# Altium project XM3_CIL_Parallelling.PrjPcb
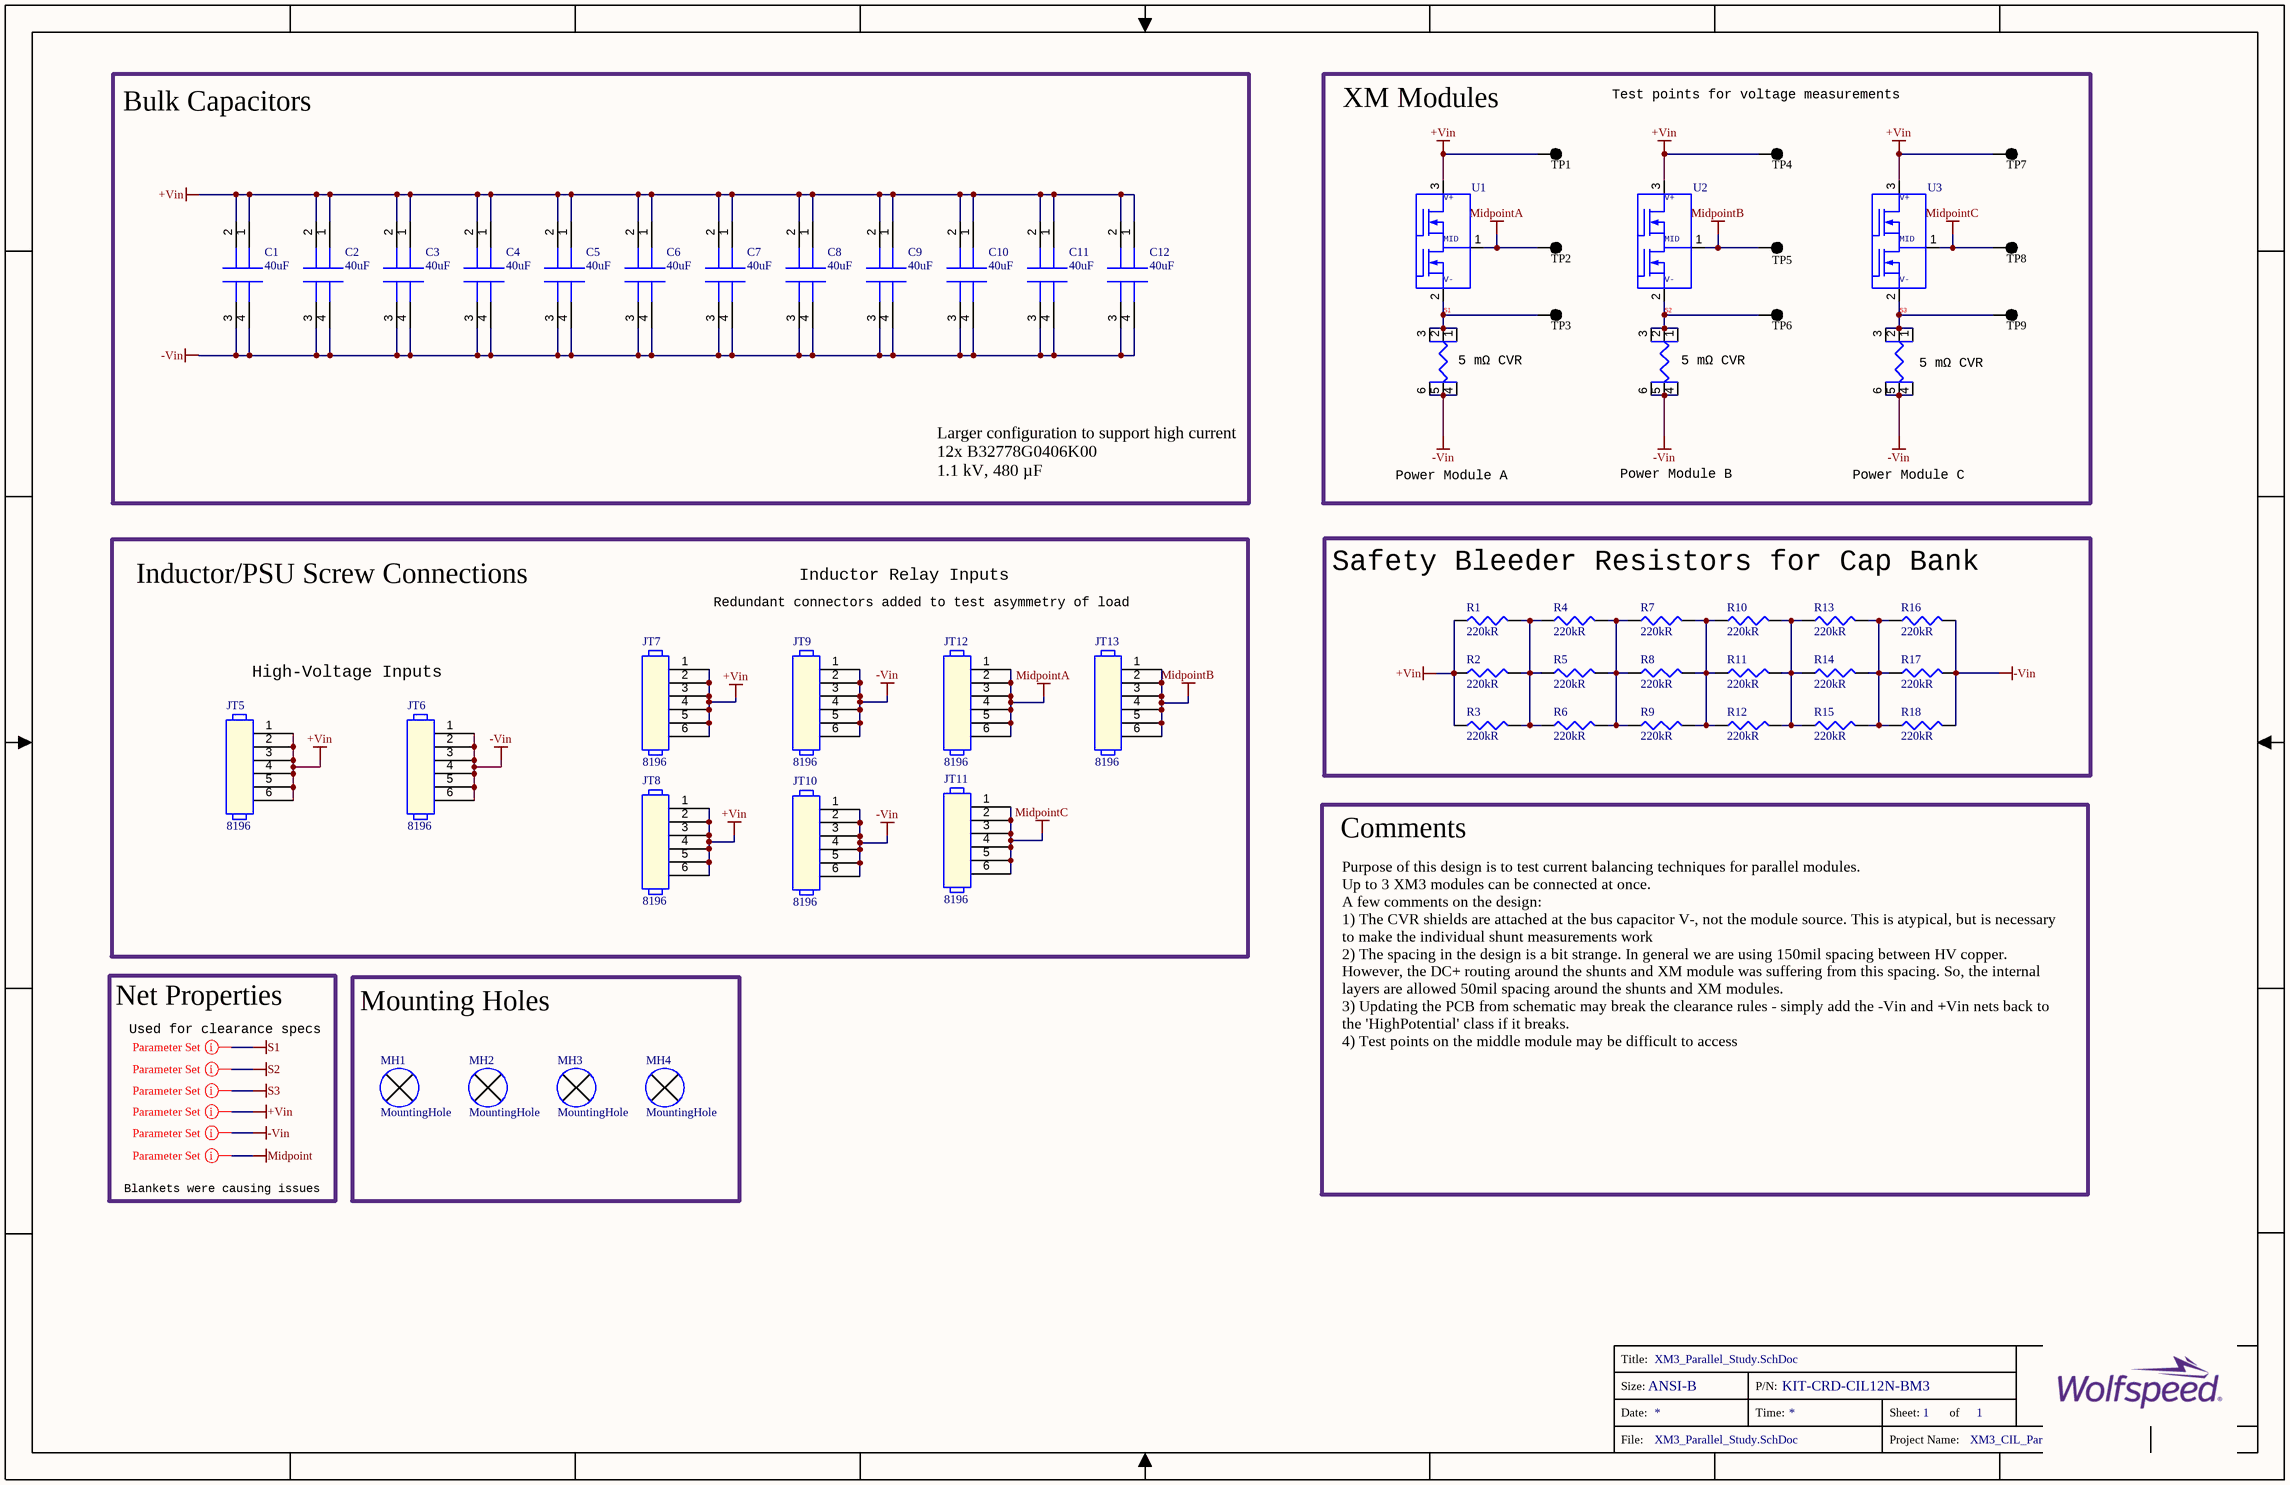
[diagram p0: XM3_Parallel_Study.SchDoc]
1 sheet, 58 parts. Net scope: global (net labels, ports and power ports of the same name join across sheets).
Board file: XM3_Parallel_Study.PcbDoc

## Sheet XM3_Parallel_Study.SchDoc
size 431 x 279 mm; DocumentNumber: KIT-CRD-CIL12N-BM3; Revision: 01; SheetNumber: 1; SheetTotal: 1

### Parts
C1  value 40uF  [C4AQSBW5220A3NJ]  (hidden comment: B32778G0406K000)
C2  value 40uF  [C4AQSBW5220A3NJ]  (hidden comment: B32778G0406K000)
C3  value 40uF  [C4AQSBW5220A3NJ]  (hidden comment: B32778G0406K000)
C4  value 40uF  [C4AQSBW5220A3NJ]  (hidden comment: B32778G0406K000)
C5  value 40uF  [C4AQSBW5220A3NJ]  (hidden comment: B32778G0406K000)
C6  value 40uF  [C4AQSBW5220A3NJ]  (hidden comment: B32778G0406K000)
C7  value 40uF  [C4AQSBW5220A3NJ]  (hidden comment: B32778G0406K000)
C8  value 40uF  [C4AQSBW5220A3NJ]  (hidden comment: B32778G0406K000)
C9  value 40uF  [C4AQSBW5220A3NJ]  (hidden comment: B32778G0406K000)
C10  value 40uF  [C4AQSBW5220A3NJ]  (hidden comment: B32778G0406K000)
C11  value 40uF  [C4AQSBW5220A3NJ]  (hidden comment: B32778G0406K000)
C12  value 40uF  [C4AQSBW5220A3NJ]  (hidden comment: B32778G0406K000)
JT5  8196  [8196]
JT6  8196  [8196]
JT7  8196  [8196]
JT8  8196  [8196]
JT9  8196  [8196]
JT10  8196  [8196]
JT11  8196  [8196]
JT12  8196  [8196]
JT13  8196  [8196]
MH1  MountingHole  [MountingHole4mm5]
MH2  MountingHole  [MountingHole4mm5]
MH3  MountingHole  [MountingHole4mm5]
MH4  MountingHole  [MountingHole4mm5]
R1  Resistance: 220kR  [RESC6432X06N]  (hidden comment: 2176071-6)
R2  Resistance: 220kR  [RESC6432X06N]  (hidden comment: 2176071-6)
R3  Resistance: 220kR  [RESC6432X06N]  (hidden comment: 2176071-6)
R4  Resistance: 220kR  [RESC6432X06N]  (hidden comment: 2176071-6)
R5  Resistance: 220kR  [RESC6432X06N]  (hidden comment: 2176071-6)
R6  Resistance: 220kR  [RESC6432X06N]  (hidden comment: 2176071-6)
R7  Resistance: 220kR  [RESC6432X06N]  (hidden comment: 2176071-6)
R8  Resistance: 220kR  [RESC6432X06N]  (hidden comment: 2176071-6)
R9  Resistance: 220kR  [RESC6432X06N]  (hidden comment: 2176071-6)
R10  Resistance: 220kR  [RESC6432X06N]  (hidden comment: 2176071-6)
R11  Resistance: 220kR  [RESC6432X06N]  (hidden comment: 2176071-6)
R12  Resistance: 220kR  [RESC6432X06N]  (hidden comment: 2176071-6)
R13  Resistance: 220kR  [RESC6432X06N]  (hidden comment: 2176071-6)
R14  Resistance: 220kR  [RESC6432X06N]  (hidden comment: 2176071-6)
R15  Resistance: 220kR  [RESC6432X06N]  (hidden comment: 2176071-6)
R16  Resistance: 220kR  [RESC6432X06N]  (hidden comment: 2176071-6)
R17  Resistance: 220kR  [RESC6432X06N]  (hidden comment: 2176071-6)
R18  Resistance: 220kR  [RESC6432X06N]  (hidden comment: 2176071-6)
R19  W-2-005-2FC  [W-2-005-2FC_3Hole]  (value not drawn)
R20  W-2-005-2FC  [W-2-005-2FC_3Hole]  (value not drawn)
R21  W-2-005-2FC  [W-2-005-2FC_3Hole]  (value not drawn)
TP1  5011  [KSTN-5011_V]  (value not drawn)
TP2  5011  [KSTN-5011_V]  (value not drawn)
TP3  5011  [KSTN-5011_V]  (value not drawn)
TP4  5011  [KSTN-5011_V]  (value not drawn)
TP5  5011  [KSTN-5011_V]  (value not drawn)
TP6  5011  [KSTN-5011_V]  (value not drawn)
TP7  5011  [KSTN-5011_V]  (value not drawn)
TP8  5011  [KSTN-5011_V]  (value not drawn)
TP9  5011  [KSTN-5011_V]  (value not drawn)
U1  XM_Module  [XM Module]  (value not drawn)
U2  XM_Module  [XM Module]  (value not drawn)
U3  XM_Module  [XM Module]  (value not drawn)

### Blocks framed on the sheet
Safety Bleeder Resistors for Cap Bank: R1-R18

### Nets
+Vin: C1.1 C1.2 C2.1 C2.2 C3.1 C3.2 C4.1 C4.2 C5.1 C5.2 C6.1 C6.2 C7.1 C7.2 C8.1 C8.2 C9.1 C9.2 C10.1 C10.2 C11.1 C11.2 C12.1 C12.2 JT5.1 JT5.2 JT5.3 JT5.4 JT5.5 JT5.6 JT7.1 JT7.2 JT7.3 JT7.4 JT7.5 JT7.6 JT8.1 JT8.2 JT8.3 JT8.4 JT8.5 JT8.6 R1.1 R2.1 R3.1 TP1.1 TP4.1 TP7.1 U1.3(MID) U2.3(MID) U3.3(MID)
-Vin: C1.3 C1.4 C2.3 C2.4 C3.3 C3.4 C4.3 C4.4 C5.3 C5.4 C6.3 C6.4 C7.3 C7.4 C8.3 C8.4 C9.3 C9.4 C10.3 C10.4 C11.3 C11.4 C12.3 C12.4 JT6.1 JT6.2 JT6.3 JT6.4 JT6.5 JT6.6 JT9.1 JT9.2 JT9.3 JT9.4 JT9.5 JT9.6 JT10.1 JT10.2 JT10.3 JT10.4 JT10.5 JT10.6 R16.2 R17.2 R18.2 R19.4 R19.5 R19.6 R20.4 R20.5 R20.6 R21.4 R21.5 R21.6
MidpointA: JT12.1 JT12.2 JT12.3 JT12.4 JT12.5 JT12.6 TP2.1 U1.1(V+)
MidpointB: JT13.1 JT13.2 JT13.3 JT13.4 JT13.5 JT13.6 TP5.1 U2.1(V+)
MidpointC: JT11.1 JT11.2 JT11.3 JT11.4 JT11.5 JT11.6 TP8.1 U3.1(V+)
S1: R19.1 R19.2 R19.3 TP3.1 U1.2(V-)
S2: R20.1 R20.2 R20.3 TP6.1 U2.2(V-)
S3: R21.1 R21.2 R21.3 TP9.1 U3.2(V-)
NetR1_2: R1.2 R2.2 R3.2 R4.1 R5.1 R6.1
NetR4_2: R4.2 R5.2 R6.2 R7.1 R8.1 R9.1
NetR7_2: R7.2 R8.2 R9.2 R10.1 R11.1 R12.1
NetR10_2: R10.2 R11.2 R12.2 R13.1 R14.1 R15.1
NetR13_2: R13.2 R14.2 R15.2 R16.1 R17.1 R18.1

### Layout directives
net class HighPotential: +Vin, -Vin, Midpoint, S1, S2, S3

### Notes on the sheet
- Test points for voltage measurements
- Bulk Capacitors
- (near TP1) XM Modules
- (near R19) 5 mΩ CVR
- (near R20) 5 mΩ CVR
- (near R21) 5 mΩ CVR
- Larger configuration to support high current
  12x B32778G0406K00
  1.1 kV, 480 µF
- Power Module A
- Power Module B
- Power Module C
- Inductor/PSU Screw Connections
- Redundant connectors added to test asymmetry of load
- Inductor Relay Inputs
- High-Voltage Inputs
- Comments
- Net Properties
- Used for clearance specs
- Mounting Holes
- Purpose of this design is to test current balancing techniques for parallel modules.
  Up to 3 XM3 modules can be connected at once.
  A few comments on the design:
  1) The CVR shields are attached at the bus capacitor V-, not the module source. This is atypical, but is necessary to make the individual shunt measurements work
  2) The spacing in the design is a bit strange. In general we are using 150mil spacing between HV copper. However, the DC+ routing around the shunts and XM module was suffering from this spacing. So, the internal layers are allowed 50mil spacing around the shunts and XM modules.
  3) Updating the PCB from schematic may break the clearance rules - simply add the -Vin and +Vin nets back to the 'HighPotential' class if it breaks.
  4) Test points on the middle module may be difficult to access
- Blankets were causing issues

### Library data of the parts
C1-C12 = B32778G0406K000: B32778G0406K000 Unchecked Film; Metallized Polypropylene; DC Link; C4AQ; Automotive Grade; 40 uF; 5%; 1; 50 Film Capacitors 8.13; Manufacturer: Kemet; Voltage Rating: 1500VDC
JT5-JT13 = Conn Plug 6: TERMINAL SCREW PC HEAVY DUTY; Manufacturer: Keystone Electronics; PART_NUMBER: TMP-963; CLASS: IO
R1-R18 = 2176071-6: Res Thick Film 2512 220K Ohm 1% 2W ±100ppm/°C Molded SMD T/R; Manufacturer: TE Connectivity
TP1-TP9 = 5011: Test Point, Black, Through Hole, RoHS, Bulk; Manufacturer: Keystone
